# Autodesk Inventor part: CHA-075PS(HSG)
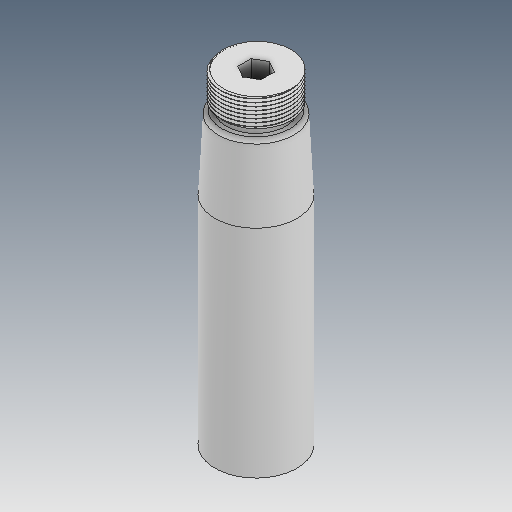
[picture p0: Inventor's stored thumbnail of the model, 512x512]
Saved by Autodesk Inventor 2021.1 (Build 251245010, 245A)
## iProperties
Created: 2021-05
Part Number: CHA-075PS(HSG)
Material: Ogólny
Document SubType Name: Modeling
Designer: user
Density: 1 g/cm^3
Appearance: Domyślna
Author: user
Revision Number: ÈÎºÎ
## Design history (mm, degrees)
feature "µ¹½Ç2"
node "Bryła1"
